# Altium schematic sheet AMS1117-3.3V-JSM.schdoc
size 127 x 101 mm
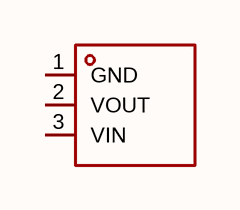
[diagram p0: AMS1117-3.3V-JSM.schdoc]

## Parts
U?  ams1117-3.3v-jsm  [SOT-89-3_L4.5-W2.5-P1.50-LS4.2-TL]  (value not drawn)

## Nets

Not connected (* = marked no-connect by the designer): U? 1(GND) 2(VOUT) 3(VIN)

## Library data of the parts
U? = ams1117-3.3v-jsm: 输出极性:正极;工作电压:15V;输出电压:3.3V;输出电流:1.2A;电源纹波抑制比(PSRR):-;输出类型:固定;; Manufacturer: JSMSEMI(杰盛微); AddInBom: yes; ModelId: c8ce1a1e9e8c456c92ba452c2c7c247d; ModelTransform: 161.417,169.291,0,0,0,0,18.622,0,0; Output Configuration: 正极; Voltage - Supply: 15V; Output Voltage: 3.3V; Output Current: 1.2A; Voltage Dropout: 1.3V@(800mA); standby current: 2mA; Output Type: 固定; Number of Outputs: 1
